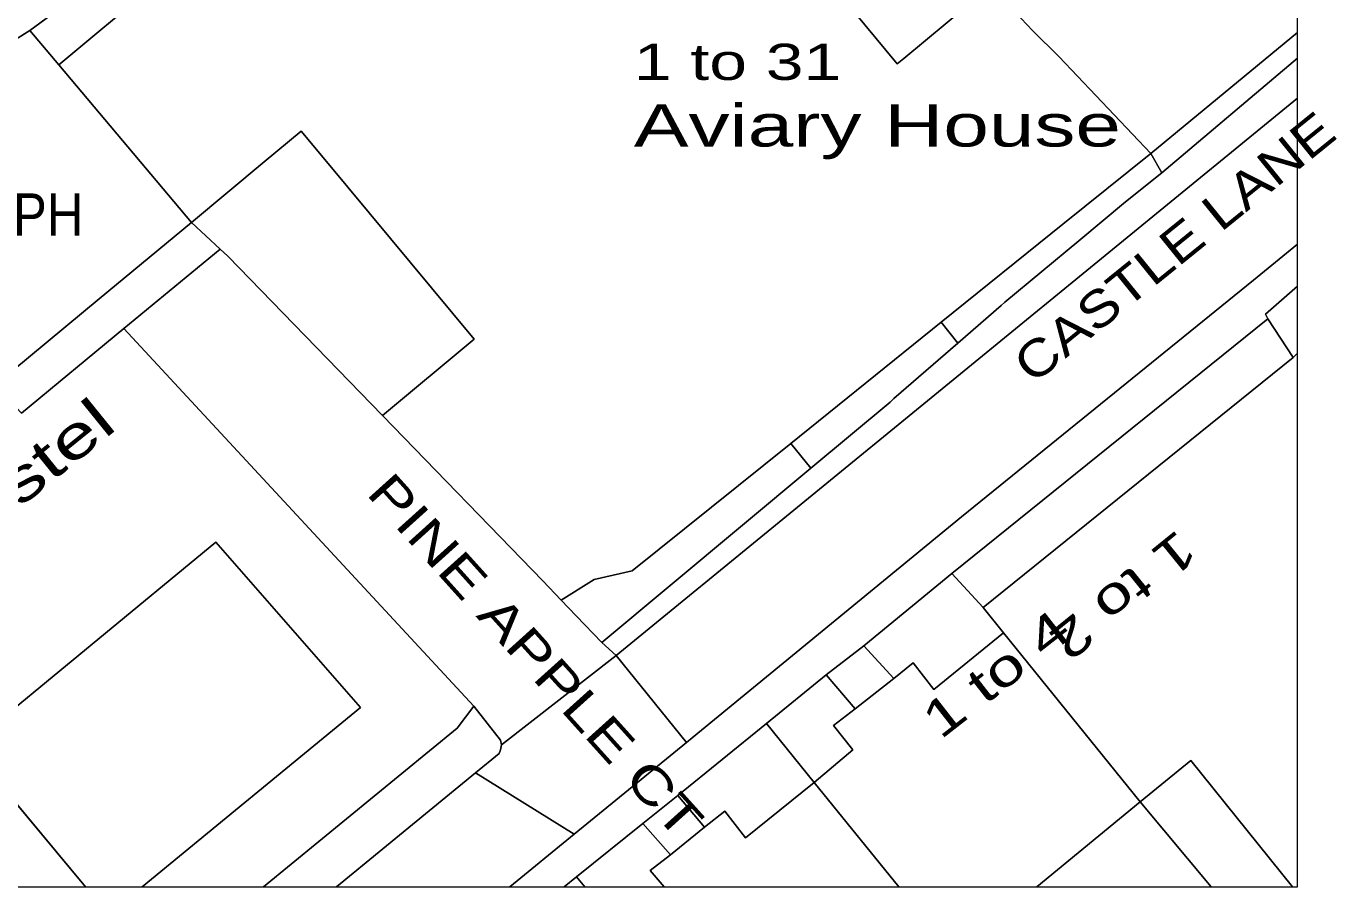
# Model space of a CAD drawing. Extents: x 528790 to 529292, y 179350 to 179856.
# Drawn here: x 529237.6 to 529291.9, y 179356 to 179391.7 of the extents above; entities that cross this region are included whole.
import ezdxf

# ---------------------------------------------------------------- set-up
doc = ezdxf.new("R2010")
doc.units = 0
doc.header["$LTSCALE"] = 0.6
for name, color, linetype, lineweight in [('1', 7, 'Continuous', 13), ('2', 7, 'Continuous', 13), ('7', 7, 'Continuous', 13)]:
    doc.layers.add(name, color=color, linetype=linetype, lineweight=lineweight)
doc.layers.add('5', color=7, linetype='Continuous')

msp = doc.modelspace()

# ---------------------------------------------------------------- linework, layer by layer
at = {"layer": '1'}
for points in [[(529290.22, 179391.418), (529290.22, 179404.418), (529286.95, 179401.85), (529285.7, 179403.3), (529287, 179404.55), (529283.15, 179408.27), (529282.3, 179409.1), (529278.1, 179404.9), (529277.5, 179405.5), (529276.15, 179404.2), (529275.6, 179404.65), (529274.3, 179403.45), (529275.3, 179402.3), (529274.95, 179401.9), (529278.5, 179398.15), (529278, 179397.7), (529280, 179395.55), (529277.6, 179393.25), (529279.25, 179391.5), (529280.35, 179390.4), (529284.15, 179386.4)], [(529260.679, 179402.3), (529260.672, 179402.309), (529257.579, 179405.947), (529257.484, 179406.058), (529254.189, 179403.633), (529251.271, 179401.486), (529237.7, 179391.5), (529238.902, 179390.073), (529239.737, 179390.767), (529241.96, 179392.613), (529249.335, 179398.739), (529251.434, 179396.217), (529253.034, 179397.482), (529253.726, 179397.398), (529254.283, 179397.433), (529254.606, 179397.504), (529255.254, 179397.795)], [(529277.505, 179393.329), (529277.3, 179393.5), (529274.9, 179396.05), (529272.816, 179397.884), (529269.491, 179395.124), (529270.555, 179393.842), (529273.644, 179390.123), (529273.91, 179390.344)], [(529244.4, 179383.55), (529238.902, 179390.073), (529237.7, 179391.5), (529228.6, 179385.8), (529228.95, 179385.3), (529236.25, 179376.8), (529240.569, 179380.377)], [(529290.22, 179391.418), (529284.15, 179386.4), (529284.6, 179385.6), (529290.22, 179390.349)], [(529290.22, 179390.349), (529284.6, 179385.6), (529283.1, 179384.4), (529281.158, 179382.788), (529278.1, 179380.25), (529277.95, 179380.1), (529276.154, 179378.546), (529273.5, 179376.25), (529273.35, 179376.1), (529270.059, 179373.36), (529261.4, 179366.15), (529262, 179365.6), (529290.22, 179388.694)], [(529290.22, 179382.648), (529290.22, 179388.694), (529262, 179365.6), (529264.91, 179362), (529265.15, 179362.2), (529276.3, 179371.35), (529288.4, 179381.15)], [(529252.307, 179375.547), (529256.112, 179378.707), (529249.99, 179386.077), (529248.949, 179387.33), (529247.415, 179386.056), (529244.4, 179383.55), (529245.592, 179382.438), (529245.9, 179382.15)], [(529277.95, 179380.1), (529278.1, 179380.25), (529281.158, 179382.788), (529283.1, 179384.4), (529284.6, 179385.6), (529284.15, 179386.4), (529280.505, 179383.468), (529275.459, 179379.409), (529276.154, 179378.546)], [(529241.6, 179379.15), (529245.592, 179382.438), (529244.4, 179383.55), (529240.569, 179380.377), (529236.25, 179376.8), (529237.35, 179375.65)], [(529245.9, 179382.15), (529245.592, 179382.438), (529241.6, 179379.15), (529256.1, 179363.5), (529257.2, 179362.1), (529257.25, 179361.9), (529262, 179365.6), (529261.4, 179366.15), (529260.343, 179367.25), (529259.717, 179367.897), (529258.95, 179368.7), (529252.307, 179375.547)], [(529257.586, 179356.024), (529259.845, 179356.024), (529260.35, 179356.43), (529263.1, 179358.65), (529264.55, 179359.8), (529268.22, 179362.79), (529270.7, 179364.8), (529272.25, 179366), (529275.9, 179369), (529289, 179379.55), (529288.9, 179379.75), (529290.22, 179380.904), (529290.22, 179382.648), (529288.4, 179381.15), (529276.3, 179371.35), (529265.15, 179362.2), (529264.91, 179362), (529260.26, 179358.21)], [(529290.22, 179378.077), (529290.22, 179380.904), (529288.9, 179379.75), (529289, 179379.55), (529290.05, 179377.95), (529290.2, 179378.1)], [(529247.386, 179356.024), (529255.4, 179362.6), (529256.1, 179363.5), (529241.6, 179379.15), (529237.35, 179375.65), (529236.25, 179376.8), (529229.7, 179371.3), (529228.916, 179370.651), (529231.986, 179366.824), (529234.023, 179364.285), (529231.93, 179362.606), (529229.893, 179365.145), (529229.26, 179364.682), (529231.811, 179361.502), (529224.98, 179356.024), (529228.068, 179356.024), (529235.15, 179361.85), (529245.4, 179370.3), (529251.4, 179363.45), (529242.36, 179356.024)], [(529273.35, 179376.1), (529273.5, 179376.25), (529276.154, 179378.546), (529275.459, 179379.409), (529269.226, 179374.395), (529270.059, 179373.36)], [(529290.05, 179377.95), (529289, 179379.55), (529275.9, 179369), (529277.2, 179367.6)], [(529290.22, 179378.077), (529290.2, 179378.1), (529290.05, 179377.95), (529277.2, 179367.6), (529278.05, 179366.55), (529283.7, 179359.55), (529285.8, 179361.25), (529290.022, 179356.024), (529290.22, 179356.024)], [(529270.059, 179373.36), (529269.226, 179374.395), (529262.664, 179369.117), (529261.084, 179368.76), (529259.717, 179367.897), (529260.343, 179367.25), (529261.4, 179366.15)], [(529240.012, 179356.024), (529242.36, 179356.024), (529251.4, 179363.45), (529245.4, 179370.3), (529235.15, 179361.85)], [(529275.9, 179369), (529272.25, 179366), (529273.5, 179364.65), (529274.3, 179365.3), (529275.15, 179364.2), (529278.05, 179366.55), (529277.2, 179367.6)], [(529273.709, 179356.024), (529279.424, 179356.024), (529283.7, 179359.55), (529278.05, 179366.55), (529275.15, 179364.2), (529274.3, 179365.3), (529273.5, 179364.65), (529271.9, 179363.4), (529271, 179362.7), (529271.8, 179361.7), (529270.2, 179360.35)], [(529262, 179365.6), (529257.25, 179361.9), (529257.2, 179361.7), (529257.15, 179361.55), (529256.17, 179360.75), (529260.26, 179358.21), (529264.91, 179362)], [(529271.9, 179363.4), (529273.5, 179364.65), (529272.25, 179366), (529270.7, 179364.8)], [(529270.2, 179360.35), (529271.8, 179361.7), (529271, 179362.7), (529271.9, 179363.4), (529270.7, 179364.8), (529268.22, 179362.79)], [(529250.41, 179356.024), (529256.17, 179360.75), (529257.15, 179361.55), (529257.2, 179361.7), (529257.25, 179361.9), (529257.2, 179362.1), (529256.1, 179363.5), (529255.4, 179362.6), (529247.386, 179356.024)], [(529268.22, 179362.79), (529264.55, 179359.8), (529265.65, 179358.5), (529266.5, 179359.15), (529267.35, 179358.05), (529270.2, 179360.35)], [(529228.068, 179356.024), (529240.012, 179356.024), (529235.15, 179361.85)], [(529290.022, 179356.024), (529285.8, 179361.25), (529283.7, 179359.55), (529286.65, 179356.024)], [(529257.586, 179356.024), (529260.26, 179358.21), (529256.17, 179360.75), (529250.41, 179356.024)], [(529263.979, 179356.024), (529273.709, 179356.024), (529270.2, 179360.35), (529267.35, 179358.05), (529266.5, 179359.15), (529265.65, 179358.5), (529264.25, 179357.35), (529263.4, 179356.7)], [(529265.65, 179358.5), (529264.55, 179359.8), (529263.1, 179358.65), (529264.25, 179357.35)], [(529279.424, 179356.024), (529286.65, 179356.024), (529283.7, 179359.55)], [(529263.979, 179356.024), (529263.4, 179356.7), (529264.25, 179357.35), (529263.1, 179358.65), (529260.35, 179356.43), (529260.698, 179356.024)], [(529260.698, 179356.024), (529260.35, 179356.43), (529259.845, 179356.024)]]:
    msp.add_lwpolyline(points, close=True, dxfattribs=at)
for points in [[(529228.6, 179385.8), (529237.7, 179391.5), (529251.271, 179401.486), (529250.6, 179402.45), (529250.15, 179402.7), (529249.7, 179402.75), (529237.9, 179394.35), (529233.9, 179391.85)], [(529277.505, 179393.329), (529273.91, 179390.344), (529273.644, 179390.123), (529270.555, 179393.842)], [(529241.96, 179392.613), (529239.737, 179390.767), (529238.902, 179390.073), (529244.4, 179383.55), (529247.415, 179386.056), (529248.949, 179387.33), (529249.99, 179386.077), (529256.112, 179378.707), (529252.307, 179375.547), (529258.95, 179368.7), (529259.717, 179367.897), (529261.084, 179368.76), (529262.664, 179369.117), (529269.226, 179374.395), (529275.459, 179379.409), (529280.505, 179383.468), (529284.15, 179386.4), (529280.35, 179390.4), (529279.25, 179391.5), (529277.6, 179393.25)]]:
    msp.add_lwpolyline(points, dxfattribs=at)
at = {"layer": '2'}
for p, q in [((529237.7, 179391.5), (529251.271, 179401.486)), ((529237.7, 179391.5), (529228.6, 179385.8)), ((529237.7, 179391.5), (529238.902, 179390.073)), ((529284.15, 179386.4), (529290.22, 179391.418)), ((529238.902, 179390.073), (529244.4, 179383.55)), ((529284.6, 179385.6), (529290.22, 179390.349)), ((529290.22, 179388.694), (529262, 179365.6)), ((529284.15, 179386.4), (529284.6, 179385.6)), ((529244.4, 179383.55), (529245.592, 179382.438)), ((529241.6, 179379.15), (529245.592, 179382.438)), ((529256.1, 179363.5), (529241.6, 179379.15)), ((529275.459, 179379.409), (529269.226, 179374.395)), ((529275.459, 179379.409), (529276.154, 179378.546)), ((529275.9, 179369), (529289, 179379.55)), ((529290.05, 179377.95), (529289, 179379.55)), ((529277.2, 179367.6), (529290.05, 179377.95)), ((529269.226, 179374.395), (529270.059, 179373.36)), ((529261.4, 179366.15), (529270.059, 179373.36)), ((529272.25, 179366), (529275.9, 179369)), ((529277.2, 179367.6), (529275.9, 179369)), ((529259.717, 179367.897), (529260.343, 179367.25)), ((529260.343, 179367.25), (529261.4, 179366.15)), ((529278.05, 179366.55), (529277.2, 179367.6)), ((529262, 179365.6), (529261.4, 179366.15)), ((529283.7, 179359.55), (529278.05, 179366.55)), ((529257.25, 179361.9), (529262, 179365.6)), ((529262, 179365.6), (529264.91, 179362)), ((529270.7, 179364.8), (529272.25, 179366)), ((529272.25, 179366), (529273.5, 179364.65)), ((529268.22, 179362.79), (529270.7, 179364.8)), ((529270.7, 179364.8), (529271.9, 179363.4)), ((529271.9, 179363.4), (529273.5, 179364.65)), ((529264.55, 179359.8), (529268.22, 179362.79)), ((529270.2, 179360.35), (529268.22, 179362.79)), ((529235.15, 179361.85), (529240.012, 179356.024)), ((529260.26, 179358.21), (529264.91, 179362)), ((529256.17, 179360.75), (529250.41, 179356.024)), ((529260.26, 179358.21), (529256.17, 179360.75)), ((529270.2, 179360.35), (529273.709, 179356.024)), ((529263.1, 179358.65), (529264.55, 179359.8)), ((529264.55, 179359.8), (529265.65, 179358.5)), ((529283.7, 179359.55), (529279.424, 179356.024)), ((529286.65, 179356.024), (529283.7, 179359.55)), ((529260.35, 179356.43), (529263.1, 179358.65)), ((529264.25, 179357.35), (529263.1, 179358.65)), ((529264.25, 179357.35), (529265.65, 179358.5)), ((529257.586, 179356.024), (529260.26, 179358.21)), ((529259.845, 179356.024), (529260.35, 179356.43)), ((529260.698, 179356.024), (529260.35, 179356.43))]:
    msp.add_line(p, q, dxfattribs=at)
for points in [[(529251.434, 179396.217), (529249.335, 179398.739), (529241.96, 179392.613), (529239.737, 179390.767), (529238.902, 179390.073)], [(529277.505, 179393.329), (529273.91, 179390.344), (529273.644, 179390.123), (529270.555, 179393.842), (529269.491, 179395.124)], [(529277.6, 179393.25), (529279.25, 179391.5), (529280.35, 179390.4), (529284.15, 179386.4)], [(529244.4, 179383.55), (529247.415, 179386.056), (529248.949, 179387.33), (529249.99, 179386.077), (529256.112, 179378.707), (529252.307, 179375.547)], [(529284.15, 179386.4), (529280.505, 179383.468), (529275.459, 179379.409)], [(529276.154, 179378.546), (529277.95, 179380.1), (529278.1, 179380.25), (529281.158, 179382.788), (529283.1, 179384.4), (529284.6, 179385.6)], [(529236.25, 179376.8), (529240.569, 179380.377), (529244.4, 179383.55)], [(529252.307, 179375.547), (529245.9, 179382.15), (529245.592, 179382.438)], [(529264.91, 179362), (529265.15, 179362.2), (529276.3, 179371.35), (529288.4, 179381.15), (529290.22, 179382.648)], [(529289, 179379.55), (529288.9, 179379.75), (529290.22, 179380.904)], [(529236.25, 179376.8), (529237.35, 179375.65), (529241.6, 179379.15)], [(529270.059, 179373.36), (529273.35, 179376.1), (529273.5, 179376.25), (529276.154, 179378.546)], [(529290.05, 179377.95), (529290.2, 179378.1), (529290.22, 179378.077)], [(529252.307, 179375.547), (529258.95, 179368.7), (529259.717, 179367.897)], [(529269.226, 179374.395), (529262.664, 179369.117), (529261.084, 179368.76), (529259.717, 179367.897)], [(529235.15, 179361.85), (529245.4, 179370.3), (529251.4, 179363.45), (529242.36, 179356.024)], [(529273.5, 179364.65), (529274.3, 179365.3), (529275.15, 179364.2), (529278.05, 179366.55)], [(529247.386, 179356.024), (529255.4, 179362.6), (529256.1, 179363.5)], [(529256.1, 179363.5), (529257.2, 179362.1), (529257.25, 179361.9)], [(529270.2, 179360.35), (529271.8, 179361.7), (529271, 179362.7), (529271.9, 179363.4)], [(529257.25, 179361.9), (529257.2, 179361.7), (529257.15, 179361.55), (529256.17, 179360.75)], [(529290.022, 179356.024), (529285.8, 179361.25), (529283.7, 179359.55)], [(529265.65, 179358.5), (529266.5, 179359.15), (529267.35, 179358.05), (529270.2, 179360.35)], [(529263.979, 179356.024), (529263.4, 179356.7), (529264.25, 179357.35)]]:
    msp.add_lwpolyline(points, dxfattribs=at)
at = {"layer": '7'}
msp.add_lwpolyline([(528790.22, 179356.024), (529290.22, 179356.024), (529290.22, 179856.024), (528790.22, 179856.024)], close=True, dxfattribs=at)

# ---------------------------------------------------------------- texts
at = {"layer": '5'}
for s, height, width, p in [('1 to 31', 1.5, 1.4, (529262.73, 179389.45)), ('Aviary House', 1.75, 1.45, (529262.73, 179386.69)), ('PH', 1.75, 0.9, (529237, 179383))]:
    msp.add_text(s, height=height, dxfattribs=dict(at, width=width)).set_placement(p)
for s, height, rotation, width, p in [('CASTLE LANE', 1.5, 39, 1.2, (529279.25, 179376.8)), ('Victoria Hostel', 1.75, 39, 1.45, (529224.38, 179361.26)), ('PINE APPLE CT', 1.5, 312, 1.3, (529251.6, 179372.3)), ('1 to 2', 1.5, 219, 1.4, (529285.28, 179370.88)), ('1 to 4', 1.5, 38, 1.4, (529275.43, 179362.09))]:
    msp.add_text(s, height=height, rotation=rotation, dxfattribs=dict(at, width=width)).set_placement(p)

doc.saveas('drawing.dxf')
